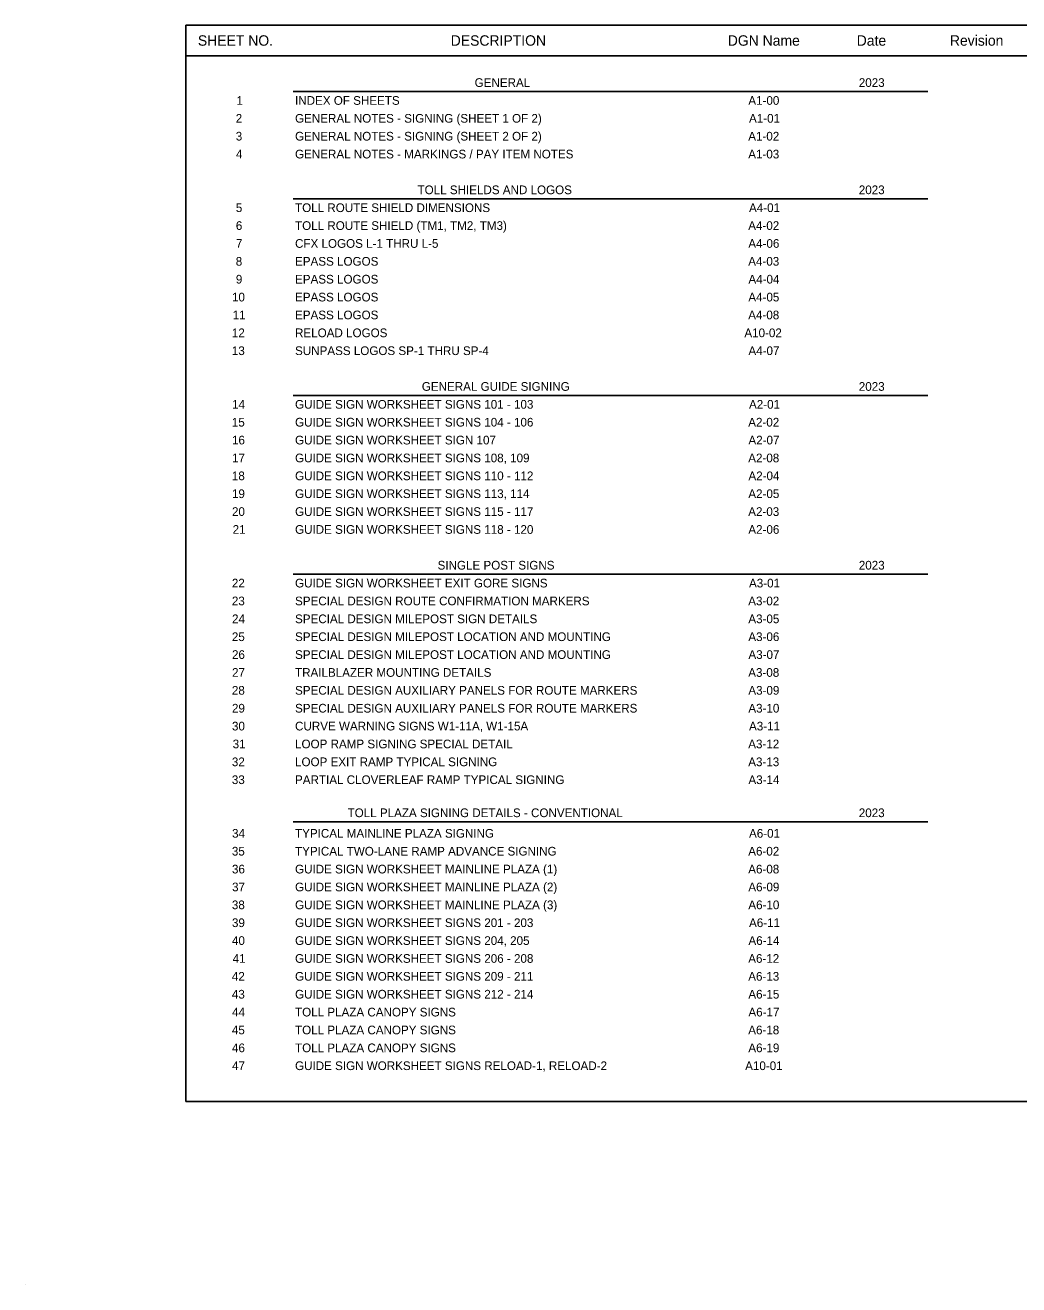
# Model space of a CAD drawing. Extents: x 2479979.8 to 2480018.9, y 3680687.9 to 3680700.6.
# Drawn here: x 2479979.84 to 2479989.84, y 3680687.87 to 3680700.55 of the extents above; entities that cross this region are included whole.
import ezdxf

# ---------------------------------------------------------------- set-up
doc = ezdxf.new("R2010")
doc.units = 0
for name, color, linetype in [('AdhocPoint_dp', 7, 'Continuous'), ('SumBoxLines_dp', 7, 'Continuous'), ('TextLabel', 7, 'Continuous')]:
    doc.layers.add(name, color=color, linetype=linetype)

msp = doc.modelspace()

# ---------------------------------------------------------------- linework, layer by layer
at = {"layer": 'AdhocPoint_dp'}
msp.add_line((2479979.842, 3680687.871), (2479979.842, 3680687.871), dxfattribs=at)
at = {"layer": 'SumBoxLines_dp'}
for p, q in [((2479981.458, 3680700.555), (2479998.85, 3680700.555)), ((2479981.458, 3680700.555), (2479981.458, 3680689.717)), ((2479981.458, 3680700.247), (2479998.85, 3680700.247)), ((2479981.458, 3680700.247), (2479998.85, 3680700.247)), ((2479982.538, 3680699.887), (2479988.928, 3680699.887)), ((2479982.538, 3680699.887), (2479988.928, 3680699.887)), ((2479982.538, 3680698.807), (2479988.928, 3680698.807)), ((2479982.538, 3680698.807), (2479988.928, 3680698.807)), ((2479982.538, 3680696.827), (2479988.928, 3680696.827)), ((2479982.538, 3680696.827), (2479988.928, 3680696.827)), ((2479982.538, 3680695.027), (2479988.928, 3680695.027)), ((2479982.538, 3680695.027), (2479988.928, 3680695.027)), ((2479982.538, 3680692.533), (2479988.928, 3680692.533)), ((2479982.538, 3680692.533), (2479988.928, 3680692.533)), ((2479981.458, 3680689.717), (2479998.85, 3680689.717))]:
    msp.add_line(p, q, dxfattribs=at)

# ---------------------------------------------------------------- texts
at = {"layer": 'TextLabel'}
for s, height, p in [('SHEET NO.', 0.105, (2479981.58, 3680700.348)), ('DESCRIPTION', 0.105, (2479984.125, 3680700.348)), ('DGN Name', 0.105, (2479986.914, 3680700.348)), ('Date', 0.105, (2479988.212, 3680700.348)), ('Revision', 0.105, (2479989.15, 3680700.348)), ('GENERAL', 0.0875, (2479984.366, 3680699.933)), ('2023', 0.0875, (2479988.233, 3680699.933)), ('1', 0.0875, (2479981.969, 3680699.753)), ('INDEX OF SHEETS', 0.0875, (2479982.558, 3680699.753)), ('A1-00', 0.0875, (2479987.121, 3680699.753)), ('2', 0.0875, (2479981.961, 3680699.573)), ('GENERAL NOTES - SIGNING (SHEET 1 OF 2)', 0.0875, (2479982.558, 3680699.573)), ('A1-01', 0.0875, (2479987.128, 3680699.573)), ('3', 0.0875, (2479981.961, 3680699.393)), ('GENERAL NOTES - SIGNING (SHEET 2 OF 2)', 0.0875, (2479982.558, 3680699.393)), ('A1-02', 0.0875, (2479987.12, 3680699.393)), ('4', 0.0875, (2479981.963, 3680699.213)), ('GENERAL NOTES - MARKINGS / PAY ITEM NOTES', 0.0875, (2479982.558, 3680699.213)), ('A1-03', 0.0875, (2479987.12, 3680699.213)), ('TOLL SHIELDS AND LOGOS', 0.0875, (2479983.791, 3680698.853)), ('2023', 0.0875, (2479988.233, 3680698.853)), ('5', 0.0875, (2479981.962, 3680698.673)), ('TOLL ROUTE SHIELD DIMENSIONS', 0.0875, (2479982.558, 3680698.673)), ('A4-01', 0.0875, (2479987.128, 3680698.673)), ('6', 0.0875, (2479981.962, 3680698.493)), ('TOLL ROUTE SHIELD (TM1, TM2, TM3)', 0.0875, (2479982.558, 3680698.493)), ('A4-02', 0.0875, (2479987.12, 3680698.493)), ('7', 0.0875, (2479981.963, 3680698.313)), ('CFX LOGOS L-1 THRU L-5', 0.0875, (2479982.558, 3680698.313)), ('A4-06', 0.0875, (2479987.121, 3680698.313)), ('8', 0.0875, (2479981.961, 3680698.133)), ('EPASS LOGOS', 0.0875, (2479982.558, 3680698.133)), ('A4-03', 0.0875, (2479987.12, 3680698.133)), ('9', 0.0875, (2479981.962, 3680697.953)), ('EPASS LOGOS', 0.0875, (2479982.558, 3680697.953)), ('A4-04', 0.0875, (2479987.122, 3680697.953)), ('10', 0.0875, (2479981.923, 3680697.773)), ('EPASS LOGOS', 0.0875, (2479982.558, 3680697.773)), ('A4-05', 0.0875, (2479987.121, 3680697.773)), ('11', 0.0875, (2479981.93, 3680697.593)), ('EPASS LOGOS', 0.0875, (2479982.558, 3680697.593)), ('A4-08', 0.0875, (2479987.12, 3680697.593)), ('12', 0.0875, (2479981.922, 3680697.413)), ('RELOAD LOGOS', 0.0875, (2479982.558, 3680697.413)), ('A10-02', 0.0875, (2479987.081, 3680697.413)), ('13', 0.0875, (2479981.922, 3680697.233)), ('SUNPASS LOGOS SP-1 THRU SP-4', 0.0875, (2479982.558, 3680697.233)), ('A4-07', 0.0875, (2479987.122, 3680697.233)), ('GENERAL GUIDE SIGNING', 0.0875, (2479983.834, 3680696.873)), ('2023', 0.0875, (2479988.233, 3680696.873)), ('14', 0.0875, (2479981.924, 3680696.693)), ('GUIDE SIGN WORKSHEET SIGNS 101 - 103', 0.0875, (2479982.558, 3680696.693)), ('A2-01', 0.0875, (2479987.128, 3680696.693)), ('15', 0.0875, (2479981.922, 3680696.513)), ('GUIDE SIGN WORKSHEET SIGNS 104 - 106', 0.0875, (2479982.558, 3680696.513)), ('A2-02', 0.0875, (2479987.12, 3680696.513)), ('16', 0.0875, (2479981.923, 3680696.333)), ('GUIDE SIGN WORKSHEET SIGN 107', 0.0875, (2479982.558, 3680696.333)), ('A2-07', 0.0875, (2479987.122, 3680696.333)), ('17', 0.0875, (2479981.924, 3680696.153)), ('GUIDE SIGN WORKSHEET SIGNS 108, 109', 0.0875, (2479982.558, 3680696.153)), ('A2-08', 0.0875, (2479987.12, 3680696.153)), ('18', 0.0875, (2479981.922, 3680695.973)), ('GUIDE SIGN WORKSHEET SIGNS 110 - 112', 0.0875, (2479982.558, 3680695.973)), ('A2-04', 0.0875, (2479987.122, 3680695.973)), ('19', 0.0875, (2479981.923, 3680695.793)), ('GUIDE SIGN WORKSHEET SIGNS 113, 114', 0.0875, (2479982.558, 3680695.793)), ('A2-05', 0.0875, (2479987.121, 3680695.793)), ('20', 0.0875, (2479981.923, 3680695.613)), ('GUIDE SIGN WORKSHEET SIGNS 115 - 117', 0.0875, (2479982.558, 3680695.613)), ('A2-03', 0.0875, (2479987.12, 3680695.613)), ('21', 0.0875, (2479981.93, 3680695.433)), ('GUIDE SIGN WORKSHEET SIGNS 118 - 120', 0.0875, (2479982.558, 3680695.433)), ('A2-06', 0.0875, (2479987.121, 3680695.433)), ('SINGLE POST SIGNS', 0.0875, (2479983.993, 3680695.073)), ('2023', 0.0875, (2479988.233, 3680695.073)), ('22', 0.0875, (2479981.922, 3680694.893)), ('GUIDE SIGN WORKSHEET EXIT GORE SIGNS', 0.0875, (2479982.558, 3680694.893)), ('A3-01', 0.0875, (2479987.128, 3680694.893)), ('23', 0.0875, (2479981.922, 3680694.713)), ('SPECIAL DESIGN ROUTE CONFIRMATION MARKERS', 0.0875, (2479982.558, 3680694.713)), ('A3-02', 0.0875, (2479987.12, 3680694.713)), ('24', 0.0875, (2479981.924, 3680694.533)), ('SPECIAL DESIGN MILEPOST SIGN DETAILS', 0.0875, (2479982.558, 3680694.533)), ('A3-05', 0.0875, (2479987.121, 3680694.533)), ('25', 0.0875, (2479981.922, 3680694.353)), ('SPECIAL DESIGN MILEPOST LOCATION AND MOUNTING', 0.0875, (2479982.558, 3680694.353)), ('A3-06', 0.0875, (2479987.121, 3680694.353)), ('26', 0.0875, (2479981.923, 3680694.173)), ('SPECIAL DESIGN MILEPOST LOCATION AND MOUNTING', 0.0875, (2479982.558, 3680694.173)), ('A3-07', 0.0875, (2479987.122, 3680694.173)), ('27', 0.0875, (2479981.924, 3680693.993)), ('TRAILBLAZER MOUNTING DETAILS', 0.0875, (2479982.558, 3680693.993)), ('A3-08', 0.0875, (2479987.12, 3680693.993)), ('28', 0.0875, (2479981.922, 3680693.813)), ('SPECIAL DESIGN AUXILIARY PANELS FOR ROUTE MARKERS', 0.0875, (2479982.558, 3680693.813)), ('A3-09', 0.0875, (2479987.121, 3680693.813)), ('29', 0.0875, (2479981.923, 3680693.633)), ('SPECIAL DESIGN AUXILIARY PANELS FOR ROUTE MARKERS', 0.0875, (2479982.558, 3680693.633)), ('A3-10', 0.0875, (2479987.121, 3680693.633)), ('30', 0.0875, (2479981.923, 3680693.453)), ('CURVE WARNING SIGNS W1-11A, W1-15A', 0.0875, (2479982.558, 3680693.453)), ('A3-11', 0.0875, (2479987.128, 3680693.453)), ('31', 0.0875, (2479981.93, 3680693.273)), ('LOOP RAMP SIGNING SPECIAL DETAIL', 0.0875, (2479982.558, 3680693.273)), ('A3-12', 0.0875, (2479987.12, 3680693.273)), ('32', 0.0875, (2479981.922, 3680693.093)), ('LOOP EXIT RAMP TYPICAL SIGNING', 0.0875, (2479982.558, 3680693.093)), ('A3-13', 0.0875, (2479987.12, 3680693.093)), ('33', 0.0875, (2479981.922, 3680692.913)), ('PARTIAL CLOVERLEAF RAMP TYPICAL SIGNING', 0.0875, (2479982.558, 3680692.913)), ('A3-14', 0.0875, (2479987.122, 3680692.913)), ('TOLL PLAZA SIGNING DETAILS - CONVENTIONAL', 0.0875, (2479983.087, 3680692.58)), ('2023', 0.0875, (2479988.233, 3680692.58)), ('34', 0.0875, (2479981.924, 3680692.373)), ('TYPICAL MAINLINE PLAZA SIGNING', 0.0875, (2479982.558, 3680692.373)), ('A6-01', 0.0875, (2479987.128, 3680692.373)), ('35', 0.0875, (2479981.922, 3680692.193)), ('TYPICAL TWO-LANE RAMP ADVANCE SIGNING', 0.0875, (2479982.558, 3680692.193)), ('A6-02', 0.0875, (2479987.12, 3680692.193)), ('36', 0.0875, (2479981.923, 3680692.013)), ('GUIDE SIGN WORKSHEET MAINLINE PLAZA (1)', 0.0875, (2479982.558, 3680692.013)), ('A6-08', 0.0875, (2479987.12, 3680692.013)), ('37', 0.0875, (2479981.924, 3680691.833)), ('GUIDE SIGN WORKSHEET MAINLINE PLAZA (2)', 0.0875, (2479982.558, 3680691.833)), ('A6-09', 0.0875, (2479987.121, 3680691.833)), ('38', 0.0875, (2479981.922, 3680691.653)), ('GUIDE SIGN WORKSHEET MAINLINE PLAZA (3)', 0.0875, (2479982.558, 3680691.653)), ('A6-10', 0.0875, (2479987.121, 3680691.653)), ('39', 0.0875, (2479981.923, 3680691.473)), ('GUIDE SIGN WORKSHEET SIGNS 201 - 203', 0.0875, (2479982.558, 3680691.473)), ('A6-11', 0.0875, (2479987.128, 3680691.473)), ('40', 0.0875, (2479981.923, 3680691.293)), ('GUIDE SIGN WORKSHEET SIGNS 204, 205', 0.0875, (2479982.558, 3680691.293)), ('A6-14', 0.0875, (2479987.122, 3680691.293)), ('41', 0.0875, (2479981.93, 3680691.113)), ('GUIDE SIGN WORKSHEET SIGNS 206 - 208', 0.0875, (2479982.558, 3680691.113)), ('A6-12', 0.0875, (2479987.12, 3680691.113)), ('42', 0.0875, (2479981.922, 3680690.933)), ('GUIDE SIGN WORKSHEET SIGNS 209 - 211', 0.0875, (2479982.558, 3680690.933)), ('A6-13', 0.0875, (2479987.12, 3680690.933)), ('43', 0.0875, (2479981.922, 3680690.753)), ('GUIDE SIGN WORKSHEET SIGNS 212 - 214', 0.0875, (2479982.558, 3680690.753)), ('A6-15', 0.0875, (2479987.121, 3680690.753)), ('44', 0.0875, (2479981.924, 3680690.573)), ('TOLL PLAZA CANOPY SIGNS', 0.0875, (2479982.558, 3680690.573)), ('A6-17', 0.0875, (2479987.122, 3680690.573)), ('45', 0.0875, (2479981.922, 3680690.393)), ('TOLL PLAZA CANOPY SIGNS', 0.0875, (2479982.558, 3680690.393)), ('A6-18', 0.0875, (2479987.12, 3680690.393)), ('46', 0.0875, (2479981.923, 3680690.213)), ('TOLL PLAZA CANOPY SIGNS', 0.0875, (2479982.558, 3680690.213)), ('A6-19', 0.0875, (2479987.121, 3680690.213)), ('47', 0.0875, (2479981.924, 3680690.033)), ('GUIDE SIGN WORKSHEET SIGNS RELOAD-1, RELOAD-2', 0.0875, (2479982.558, 3680690.033)), ('A10-01', 0.0875, (2479987.089, 3680690.033))]:
    msp.add_text(s, height=height, dxfattribs=at).set_placement(p)

doc.saveas('drawing.dxf')
